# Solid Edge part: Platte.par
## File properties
Sűrűség: 0,000 kg/m^3
Pontosság: 0,990
Author: bmolnar
Last saved by: bmolnar
Revision: 78
Username: bmolnar
Dokumentum tartalom típus: 0
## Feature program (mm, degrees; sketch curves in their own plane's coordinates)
base feature "unnamed BaseFeature 1"
thread "unnamed Thread 1"
thread "unnamed Thread 2"
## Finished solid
Body 1: solid body, 128 faces, 277 edges, 148 vertices, 2 internal voids.
  Faces by surface: plane 59, cylinder 44, cone 20, torus 5
  Edges by curve: line 148, circle 111, spline 18
Bounding box of the edges (mm; curved faces can reach further): 35.600 x 8.000 x 35.600, from (-17.8, -89.8, -17.8) to (17.8, -81.8, 17.8).
Cylindrical faces by radius (mm): R0.2 x12, R0.5 x12, R1.5 x2, R1.621 x2, R1.65 x2, R2 x2, R2.75 x2, R3 x2, R3.75 x2, R4.5 x4, R5 x1, R5.5 x1
Conical faces (half-angle, radius in mm at the cone's reference point): 45 deg R1.8 x2, 45 deg R1.871 x4, 45 deg R2.15 x4, 45 deg R3.15 x2, 45 deg R3.9 x4, 45 deg R5.65 x1, 60 deg R1 x2, 60 deg R1.1547 x1
Toroidal faces (ring radius, tube radius in mm): R1.6 r0.1 x2, R2.45 r0.3 x2, R4.4 r0.6 x1
Planar faces by outward normal: +x 10, +y 3, +z 7, -x 10, -y 10, -z 7, oblique 12
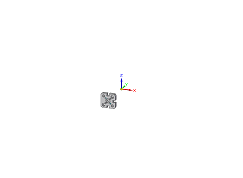
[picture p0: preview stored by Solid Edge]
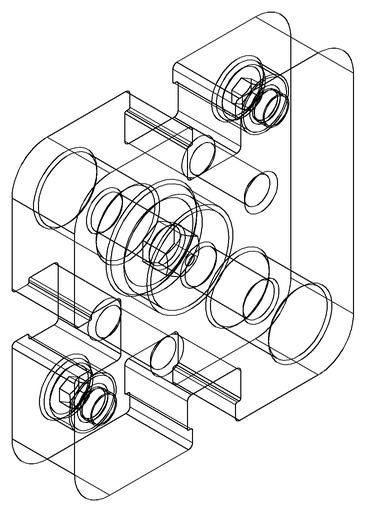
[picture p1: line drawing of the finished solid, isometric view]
